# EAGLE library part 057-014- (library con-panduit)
CONNECTOR 10-pin series 057 contact pc board low profile headers
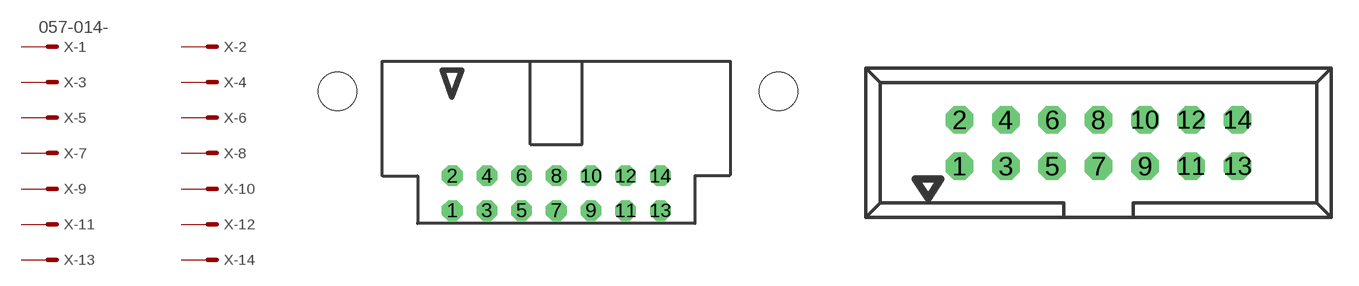
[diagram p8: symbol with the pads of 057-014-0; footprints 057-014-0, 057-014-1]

Designator prefix X; gates -1=MV -2=M -3=M -4=M -5=M -6=M -7=M -8=M -9=M -10=M -11=M -12=M -13=M -14=M

## 057-014-0 (OC_FARNELL: unknown; OC_NEWARK: unknown)  [057-014-0]
1  -1:S  pas
2  -2:S  pas
3  -3:S  pas
4  -4:S  pas
5  -5:S  pas
6  -6:S  pas
7  -7:S  pas
8  -8:S  pas
9  -9:S  pas
10  -10:S  pas
11  -11:S  pas
12  -12:S  pas
13  -13:S  pas
14  -14:S  pas

## 057-014-1 (OC_FARNELL: unknown; OC_NEWARK: unknown)  [057-014-1]
Pads as for 057-014-0

## Footprint 057-014-0 (pad centres in mm)
CONNECTOR series 057 contact pc board low profile headers angled
drill 1 octagon: 1 -7.62,-5.08; 2 -7.62,-2.54; 3 -5.08,-5.08; 4 -5.08,-2.54; 5 -2.54,-5.08; 6 -2.54,-2.54; 7 0,-5.08; 8 0,-2.54; 9 2.54,-5.08; 10 2.54,-2.54; 11 5.08,-5.08; 12 5.08,-2.54; 13 7.62,-5.08; 14 7.62,-2.54
hole 2.8 at -16.02,3.66
hole 2.8 at 16.27,3.66

## Footprint 057-014-1 (pad centres in mm)
CONNECTOR series 057 contact pc board low profile headers straight
drill 1 octagon: 1 -7.62,-1.27; 2 -7.62,1.27; 3 -5.08,-1.27; 4 -5.08,1.27; 5 -2.54,-1.27; 6 -2.54,1.27; 7 0,-1.27; 8 0,1.27; 9 2.54,-1.27; 10 2.54,1.27; 11 5.08,-1.27; 12 5.08,1.27; 13 7.62,-1.27; 14 7.62,1.27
